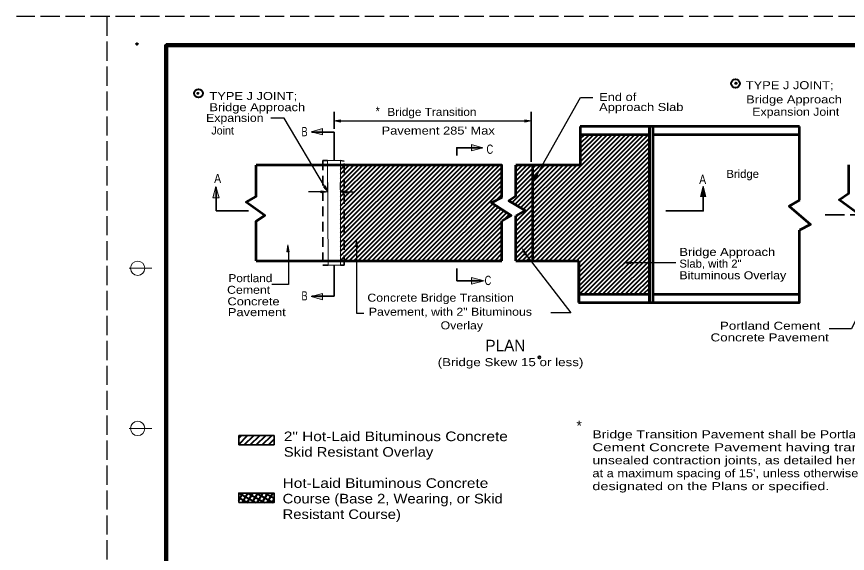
# Model space of a CAD drawing. Extents: x 36.4 to 71.7, y 0.5 to 22.5.
# Drawn here: x 36.4 to 50.93, y 13.09 to 22.48 of the extents above; entities that cross this region are included whole.
import ezdxf

# ---------------------------------------------------------------- set-up
doc = ezdxf.new("R2010")
doc.units = 0
doc.header["$LTSCALE"] = 0.056
doc.header["$PDMODE"] = 32
doc.header["$PDSIZE"] = 0.028
for name, pattern in [('LONG_DASH_SHORT_DASH', [9.9, 6, -1.2, 1.5, -1.2]), ('LONG_DASHED', [7.5, 6, -1.5]), ('MEDIUM_DASHED', [4.5, 3, -1.5])]:
    doc.linetypes.add(name, pattern=pattern)
for name, color, linetype, lineweight in [('1', 7, 'Continuous', 40), ('2', 7, 'MEDIUM_DASHED', 35), ('3', 7, 'Continuous', 13), ('5', 7, 'Continuous', 35), ('6', 7, 'Continuous', 13), ('7', 7, 'LONG_DASH_SHORT_DASH', 35)]:
    doc.layers.add(name, color=color, linetype=linetype, lineweight=lineweight)

msp = doc.modelspace()

# ---------------------------------------------------------------- hatches: boundary and pattern name
at = {"layer": '1'}
for points in [[(42.06308, 20.63383), (42.06308, 20.67133), (41.95058, 20.65258), (41.95058, 20.65258)], [(45.28767, 20.63383), (45.28767, 20.67133), (45.40017, 20.65258), (45.40017, 20.65258)], [(41.72817, 19.396), (41.72817, 19.4335), (41.84067, 19.41475), (41.84067, 19.41475)], [(42.1755, 19.396), (42.1755, 19.4335), (42.063, 19.41475), (42.063, 19.41475)]]:
    msp.add_hatch(color=256, dxfattribs=at).paths.add_polyline_path(points)
at = {"layer": '3'}
for points in [[(41.75125, 20.41192), (41.75125, 20.51883), (41.55192, 20.46525), (41.55192, 20.46525)], [(44.35408, 20.23875), (44.35408, 20.13192), (44.55333, 20.18542), (44.55333, 20.18542)], [(45.51292, 19.70658), (45.477, 19.72683), (45.43425, 19.60883), (45.43425, 19.60883)], [(39.83308, 19.30667), (39.94, 19.30667), (39.8865, 19.50592), (39.8865, 19.50592)], [(41.7995, 19.52108), (41.76733, 19.50192), (41.84075, 19.41475), (41.84075, 19.41475)], [(48.35692, 19.32992), (48.45408, 19.32992), (48.40542, 19.51108), (48.40542, 19.51108)], [(41.124, 18.362), (41.16525, 18.362), (41.14458, 18.48575), (41.14458, 18.48575)], [(42.32633, 18.4605), (42.36383, 18.4605), (42.345, 18.573), (42.345, 18.573)], [(45.28525, 18.30717), (45.318, 18.3255), (45.24675, 18.41458), (45.24675, 18.41458)], [(47.14017, 18.15467), (47.14017, 18.19592), (47.01642, 18.17533), (47.01642, 18.17533)], [(47.1415, 18.15467), (47.1415, 18.19592), (47.01775, 18.17533), (47.01775, 18.17533)], [(44.35625, 17.919), (44.35625, 17.80133), (44.57542, 17.86025), (44.57542, 17.86025)], [(41.74875, 17.52767), (41.74875, 17.6345), (41.54942, 17.581), (41.54942, 17.581)]]:
    msp.add_hatch(color=256, dxfattribs=at).paths.add_polyline_path(points)

# ---------------------------------------------------------------- linework, layer by layer
at = {"layer": '1', "linetype": 'LONG_DASHED', "lineweight": 25}
for p, q in [((71.60142, 22.47742), (36.40142, 22.47742)), ((37.97642, 22.47742), (37.97642, 0.47742))]:
    msp.add_line(p, q, dxfattribs=at)
at = {"layer": '1', "lineweight": 158}
for p, q in [((39.01808, 21.97742), (39.01808, 0.97742)), ((71.51808, 21.97742), (39.01808, 21.97742))]:
    msp.add_line(p, q, dxfattribs=at)
at = {"layer": '1', "lineweight": 35}
for p, q in [((41.95058, 20.5155), (41.95058, 20.81458)), ((45.40017, 19.93783), (45.40017, 20.81458)), ((40.28392, 15.1555), (40.28392, 14.98758)), ((40.90267, 15.1555), (40.28392, 15.1555)), ((40.90267, 14.98758), (40.90267, 15.1555)), ((40.28392, 14.98758), (40.90267, 14.98758))]:
    msp.add_line(p, q, dxfattribs=at)
at = {"layer": '1', "lineweight": 25}
for p, q in [((42.06308, 20.65258), (45.28767, 20.65258)), ((41.84075, 19.46308), (41.84075, 19.57675)), ((42.063, 19.447), (42.063, 19.57675)), ((41.61575, 19.41475), (41.50325, 19.41475)), ((41.72825, 19.41475), (41.61575, 19.41475)), ((42.1755, 19.41475), (42.288, 19.41475))]:
    msp.add_line(p, q, dxfattribs=at)
at = {"layer": '1', "lineweight": 53}
for p, q in [((46.25308, 20.55908), (46.25308, 19.88158)), ((50.08925, 20.55908), (46.25308, 20.55908)), ((50.09058, 20.55908), (46.25442, 20.55908)), ((47.46842, 17.47717), (47.46842, 20.55908)), ((47.46975, 17.47717), (47.46975, 20.55908)), ((47.53175, 17.47717), (47.53175, 20.55908)), ((47.53308, 17.47717), (47.53308, 20.55908)), ((50.09058, 19.27008), (50.09058, 20.55908)), ((47.46842, 20.413), (46.25308, 20.413)), ((47.46975, 20.413), (46.25442, 20.413)), ((50.08925, 20.413), (47.53175, 20.413)), ((50.09058, 20.413), (47.53308, 20.413)), ((45.12758, 19.33533), (45.12758, 19.88158)), ((45.42783, 18.20783), (45.42783, 19.88158)), ((44.88708, 18.20783), (44.88708, 18.90442)), ((45.12758, 18.20783), (45.12758, 18.99642)), ((40.58708, 18.20783), (44.88708, 18.20783)), ((45.12758, 18.20783), (46.22908, 18.20783)), ((46.22775, 18.20783), (46.22775, 17.47717)), ((46.22908, 18.20783), (46.22908, 17.47717)), ((46.22775, 17.62325), (47.46842, 17.62325)), ((46.22908, 17.62325), (47.46975, 17.62325)), ((47.53175, 17.62325), (50.08925, 17.62325)), ((47.53308, 17.62325), (50.09058, 17.62325))]:
    msp.add_line(p, q, dxfattribs=at)
at = {"layer": '1'}
for p, q in [((45.12758, 18.734), (46.80658, 20.413)), ((45.12758, 18.6545), (46.88617, 20.413)), ((45.12758, 18.57492), (46.96567, 20.413)), ((45.12758, 18.49533), (47.04517, 20.413)), ((45.12758, 18.41583), (47.12475, 20.413)), ((45.12758, 18.33633), (47.20425, 20.413)), ((45.12758, 18.25675), (47.28383, 20.413)), ((45.15817, 18.20783), (47.36333, 20.413)), ((45.23775, 18.20783), (47.44292, 20.413)), ((45.31725, 18.20783), (47.46975, 20.36033)), ((46.25442, 20.33808), (46.32925, 20.413)), ((46.25442, 20.25858), (46.40883, 20.413)), ((46.25442, 20.17908), (46.48833, 20.413)), ((46.25442, 20.0995), (46.56792, 20.413)), ((46.25442, 20.01992), (46.6475, 20.413)), ((46.25442, 19.94042), (46.727, 20.413)), ((45.39683, 18.20783), (47.46975, 20.28075)), ((45.47642, 18.20783), (47.46975, 20.20117)), ((45.55592, 18.20783), (47.46975, 20.12167)), ((45.6355, 18.20783), (47.46975, 20.04208)), ((45.71508, 18.20783), (47.46975, 19.9625)), ((42.06375, 18.21575), (43.72958, 19.88158)), ((42.06375, 18.29533), (43.65, 19.88158)), ((42.06375, 18.37483), (43.5705, 19.88158)), ((42.06375, 18.45442), (43.49092, 19.88158)), ((42.06375, 18.534), (43.41142, 19.88158)), ((42.06375, 18.6135), (43.33192, 19.88158)), ((42.06375, 18.69308), (43.25233, 19.88158)), ((42.06375, 18.77267), (43.17275, 19.88158)), ((42.06375, 18.85217), (43.09325, 19.88158)), ((42.06375, 18.93175), (43.01367, 19.88158)), ((42.06375, 19.01133), (42.93408, 19.88158)), ((42.06375, 19.09083), (42.85458, 19.88158)), ((42.06375, 19.17033), (42.775, 19.88158)), ((42.06375, 19.24992), (42.69542, 19.88158)), ((42.06375, 19.32942), (42.61592, 19.88158)), ((42.06375, 19.409), (42.53633, 19.88158)), ((42.06375, 19.48858), (42.45675, 19.88158)), ((42.06375, 19.56808), (42.37725, 19.88158)), ((42.06375, 19.64767), (42.29767, 19.88158)), ((42.06375, 19.72725), (42.21817, 19.88158)), ((42.06375, 19.80675), (42.13867, 19.88158)), ((42.13533, 18.20783), (43.80908, 19.88158)), ((42.21492, 18.20783), (43.88867, 19.88158)), ((42.29442, 18.20783), (43.96825, 19.88158)), ((42.374, 18.20783), (44.04775, 19.88158)), ((42.45358, 18.20783), (44.12733, 19.88158)), ((42.53308, 18.20783), (44.20692, 19.88158)), ((42.61267, 18.20783), (44.28642, 19.88158)), ((42.69217, 18.20783), (44.366, 19.88158)), ((42.77167, 18.20783), (44.44558, 19.88158)), ((42.85125, 18.20783), (44.52508, 19.88158)), ((42.93083, 18.20783), (44.60467, 19.88158)), ((43.01033, 18.20783), (44.68417, 19.88158)), ((43.08992, 18.20783), (44.76367, 19.88158)), ((43.1695, 18.20783), (44.84325, 19.88158)), ((43.249, 18.20783), (44.88708, 19.84583)), ((43.32858, 18.20783), (44.88708, 19.76633)), ((45.06025, 19.22358), (45.71833, 19.88158)), ((45.11008, 19.19383), (45.79792, 19.88158)), ((45.12758, 19.3705), (45.63883, 19.88158)), ((45.12758, 19.45), (45.55925, 19.88158)), ((45.12758, 19.52958), (45.47967, 19.88158)), ((45.12758, 19.60908), (45.40017, 19.88158)), ((45.12758, 19.68858), (45.32058, 19.88158)), ((45.12758, 19.76817), (45.241, 19.88158)), ((45.12758, 19.84775), (45.1615, 19.88158)), ((45.12758, 18.89317), (46.11608, 19.88158)), ((45.12758, 18.89317), (46.11608, 19.88158)), ((45.12758, 18.81358), (46.19558, 19.88158)), ((45.15992, 19.16417), (45.87742, 19.88158)), ((45.20983, 19.13442), (45.95692, 19.88158)), ((45.25967, 19.10475), (46.0365, 19.88158)), ((45.79458, 18.20783), (47.46975, 19.883)), ((45.87417, 18.20783), (47.46975, 19.80342)), ((43.40817, 18.20783), (44.88708, 19.68675)), ((45.95375, 18.20783), (47.46975, 19.72383)), ((46.03325, 18.20783), (47.46975, 19.64433)), ((43.48767, 18.20783), (44.88708, 19.60717)), ((43.56725, 18.20783), (44.88708, 19.52767)), ((46.11283, 18.20783), (47.46975, 19.56483)), ((46.19242, 18.20783), (47.46975, 19.48525)), ((43.64683, 18.20783), (44.88708, 19.44808)), ((44.77675, 19.25817), (44.88708, 19.3685)), ((46.22908, 18.165), (47.46975, 19.40575)), ((46.22908, 18.08542), (47.46975, 19.32617)), ((43.72633, 18.20783), (44.72467, 19.20625)), ((43.80592, 18.20783), (44.77292, 19.17483)), ((45.01042, 19.25317), (45.02917, 19.27192)), ((46.22908, 18.00583), (47.46975, 19.24667)), ((43.88542, 18.20783), (44.82117, 19.14358)), ((43.96492, 18.20783), (44.86942, 19.11225)), ((44.0445, 18.20783), (44.91758, 19.08092)), ((44.124, 18.20783), (44.96583, 19.04958)), ((46.22908, 17.92633), (47.46975, 19.16708)), ((46.22908, 17.84675), (47.46975, 19.0875)), ((44.20358, 18.20783), (44.88708, 18.89125)), ((44.9195, 18.92358), (45.01408, 19.01825)), ((45.12758, 18.97267), (45.18075, 19.02592)), ((46.22908, 17.76717), (47.46975, 19.008)), ((46.22908, 17.68767), (47.46975, 18.92842)), ((44.28317, 18.20783), (44.88708, 18.81175)), ((46.24425, 17.62325), (47.46975, 18.84883)), ((46.32375, 17.62325), (47.46975, 18.76933)), ((44.36267, 18.20783), (44.88708, 18.73217)), ((44.44225, 18.20783), (44.88708, 18.65258)), ((46.40333, 17.62325), (47.46975, 18.68975)), ((46.48283, 17.62325), (47.46975, 18.61017)), ((44.52183, 18.20783), (44.88708, 18.57308)), ((44.60133, 18.20783), (44.88708, 18.4935)), ((46.56242, 17.62325), (47.46975, 18.53067)), ((46.642, 17.62325), (47.46975, 18.45108)), ((44.68092, 18.20783), (44.88708, 18.41392)), ((44.7605, 18.20783), (44.88708, 18.33442)), ((46.7215, 17.62325), (47.46975, 18.37158)), ((44.84, 18.20783), (44.88708, 18.25483)), ((46.80108, 17.62325), (47.46975, 18.29208)), ((46.88067, 17.62325), (47.46975, 18.2125)), ((46.96017, 17.62325), (47.46975, 18.13292)), ((47.03975, 17.62325), (47.46975, 18.05342)), ((47.11933, 17.62325), (47.46975, 17.97383)), ((47.19883, 17.62325), (47.46975, 17.89425)), ((47.27842, 17.62325), (47.46975, 17.81475)), ((47.35792, 17.62325), (47.46975, 17.73517)), ((47.43742, 17.62325), (47.46975, 17.65558)), ((40.28392, 14.99842), (40.441, 15.1555)), ((40.28392, 15.1045), (40.335, 15.1555)), ((40.37917, 14.98758), (40.54708, 15.1555)), ((40.48533, 14.98758), (40.65317, 15.1555)), ((40.59142, 14.98758), (40.75917, 15.1555)), ((40.69742, 14.98758), (40.86533, 15.1555)), ((40.8035, 14.98758), (40.90267, 15.08692)), ((40.28392, 14.01892), (40.35858, 14.14825)), ((40.29458, 14.14825), (40.58542, 13.98033)), ((40.34833, 13.98033), (40.44517, 14.14825)), ((40.43492, 13.98033), (40.53183, 14.14825)), ((40.44458, 14.14825), (40.73542, 13.98033)), ((40.5215, 13.98033), (40.61842, 14.14825)), ((40.59458, 14.14825), (40.88542, 13.98033)), ((40.60808, 13.98033), (40.705, 14.14825)), ((40.69467, 13.98033), (40.79158, 14.14825)), ((40.74458, 14.14825), (40.90267, 14.05692)), ((40.78133, 13.98033), (40.87817, 14.14825)), ((40.89458, 14.14825), (40.90267, 14.1435)), ((40.28392, 14.06775), (40.43542, 13.98033)), ((40.28392, 13.98108), (40.28542, 13.98033)), ((40.86792, 13.98033), (40.90267, 14.04075))]:
    msp.add_line(p, q, dxfattribs=at)
at = {"layer": '1', "lineweight": 13}
for p, q in [((42.06375, 19.88158), (42.06375, 18.20783)), ((38.76808, 18.07742), (38.36808, 18.07742)), ((38.76808, 15.27742), (38.36808, 15.27742))]:
    msp.add_line(p, q, dxfattribs=at)
for points in [[(42.06308, 20.63383), (42.06308, 20.67133), (41.95058, 20.65258), (41.95058, 20.65258)], [(45.28767, 20.63383), (45.28767, 20.67133), (45.40017, 20.65258), (45.40017, 20.65258)], [(41.84708, 18.13417), (42.06308, 18.13417), (42.06308, 19.96125), (41.83808, 19.96125)]]:
    msp.add_lwpolyline(points, close=True, dxfattribs=at)
at = {"layer": '1', "lineweight": 53}
for points in [[(46.25442, 20.55908), (46.25442, 19.88158), (45.12758, 19.88158)], [(40.58708, 18.20783), (40.58708, 18.89925), (40.74008, 18.99825), (40.41608, 19.23225), (40.58708, 19.33125), (40.58708, 19.88158)], [(44.88708, 19.316), (44.88708, 19.88158), (40.58708, 19.88158)], [(51.14917, 19.00392), (50.7805, 19.27175), (50.95067, 19.38883), (50.95067, 19.88608)], [(45.12758, 19.33533), (45.005, 19.25642), (45.29025, 19.0865), (45.12758, 18.99642)], [(44.88708, 19.316), (44.70367, 19.21983), (45.04517, 18.99808), (44.88708, 18.90442)], [(50.09058, 19.27008), (49.90608, 19.16392), (50.28133, 18.84567), (50.09058, 18.74283)], [(46.22775, 17.47717), (50.08925, 17.47717), (50.08925, 18.74283)], [(46.22908, 17.47717), (50.09058, 17.47717), (50.09058, 18.74283)]]:
    msp.add_lwpolyline(points, dxfattribs=at)
at = {"layer": '1', "lineweight": 25}
for points in [[(41.72817, 19.396), (41.72817, 19.4335), (41.84067, 19.41475), (41.84067, 19.41475)], [(42.1755, 19.396), (42.1755, 19.4335), (42.063, 19.41475), (42.063, 19.41475)]]:
    msp.add_lwpolyline(points, close=True, dxfattribs=at)
at = {"layer": '1', "lineweight": 35}
msp.add_lwpolyline([(40.28392, 13.98033), (40.90267, 13.98033), (40.90267, 14.14825), (40.28392, 14.14825)], close=True, dxfattribs=at)
at = {"layer": '1', "lineweight": 13}
for centre in [(38.51808, 18.07742), (38.51808, 15.27742)]:
    msp.add_circle(centre, 0.125, dxfattribs=at)
at = {"layer": '1'}
for p in [(38.50608, 21.99742), (39.01808, 21.97742)]:
    msp.add_point(p, dxfattribs=at)
at = {"layer": '2'}
for points in [[(41.83808, 19.96125), (41.757, 19.96125), (41.757, 18.13417), (41.84708, 18.13417)], [(42.06308, 18.13417), (42.12608, 18.13417), (42.12608, 19.95217), (42.06308, 19.96125)]]:
    msp.add_lwpolyline(points, dxfattribs=at)
at = {"layer": '3', "lineweight": 25}
for p, q in [((47.14358, 18.17567), (47.92508, 18.17567)), ((47.14492, 18.17567), (47.92642, 18.17567))]:
    msp.add_line(p, q, dxfattribs=at)
for points in [[(45.483, 19.68908), (46.25808, 21.06508), (46.47358, 21.06508)], [(41.78342, 19.51158), (41.0775, 20.7025), (40.84875, 20.7025)], [(42.34508, 18.46058), (42.34508, 17.29225), (42.46967, 17.29225)], [(41.15383, 18.36642), (41.15383, 17.79108), (40.864, 17.79108)], [(45.30158, 18.31633), (46.08867, 17.29883), (45.74342, 17.29883)], [(51.68808, 18.40858), (50.99792, 17.0205), (50.60792, 17.0205)]]:
    msp.add_lwpolyline(points, dxfattribs=at)
at = {"layer": '3'}
for points in [[(41.75125, 20.41192), (41.75125, 20.51883), (41.55192, 20.46525), (41.55192, 20.46525)], [(44.35408, 20.23875), (44.35408, 20.13192), (44.55333, 20.18542), (44.55333, 20.18542)], [(45.51292, 19.70658), (45.477, 19.72683), (45.43425, 19.60883), (45.43425, 19.60883)], [(39.83308, 19.30667), (39.94, 19.30667), (39.8865, 19.50592), (39.8865, 19.50592)], [(41.7995, 19.52108), (41.76733, 19.50192), (41.84075, 19.41475), (41.84075, 19.41475)], [(48.35692, 19.32992), (48.45408, 19.32992), (48.40542, 19.51108), (48.40542, 19.51108)], [(41.124, 18.362), (41.16525, 18.362), (41.14458, 18.48575), (41.14458, 18.48575)], [(42.32633, 18.4605), (42.36383, 18.4605), (42.345, 18.573), (42.345, 18.573)], [(45.28525, 18.30717), (45.318, 18.3255), (45.24675, 18.41458), (45.24675, 18.41458)], [(47.14017, 18.15467), (47.14017, 18.19592), (47.01642, 18.17533), (47.01642, 18.17533)], [(47.1415, 18.15467), (47.1415, 18.19592), (47.01775, 18.17533), (47.01775, 18.17533)], [(44.35625, 17.919), (44.35625, 17.80133), (44.57542, 17.86025), (44.57542, 17.86025)], [(41.74875, 17.52767), (41.74875, 17.6345), (41.54942, 17.581), (41.54942, 17.581)]]:
    msp.add_lwpolyline(points, close=True, dxfattribs=at)
at = {"layer": '3', "lineweight": 40}
for centre, radius in [((48.96973, 21.30742), 0.0741), ((39.58004, 21.13612), 0.07517), ((48.97607, 21.31367), 0.01235), ((39.57154, 21.13604), 0.0094)]:
    msp.add_circle(centre, radius, dxfattribs=at)
at = {"layer": '3', "lineweight": 35}
msp.add_circle((45.54242, 16.51967), 0.02052, dxfattribs=at)
at = {"layer": '5'}
for p, q in [((41.5655, 20.45925), (41.95058, 20.45925)), ((41.95058, 19.96125), (41.95058, 20.45925)), ((39.89142, 19.49217), (39.89142, 19.08025)), ((40.45842, 19.08025), (39.89142, 19.08025)), ((41.95508, 18.13417), (41.95508, 17.58825)), ((44.09533, 17.85825), (44.09533, 18.07533)), ((44.54058, 17.85825), (44.09533, 17.85825)), ((41.5655, 17.58825), (41.95508, 17.58825))]:
    msp.add_line(p, q, dxfattribs=at)
for points in [[(44.54058, 20.18533), (44.09533, 20.18533), (44.09533, 20.05067)], [(48.40542, 19.49217), (48.40542, 19.08025), (47.75083, 19.08025)]]:
    msp.add_lwpolyline(points, dxfattribs=at)
at = {"layer": '6'}
for p, q in [((45.40017, 20.65258), (45.40025, 20.65258)), ((41.95058, 20.45925), (41.95067, 20.45925)), ((45.40017, 19.88158), (45.40025, 19.88158))]:
    msp.add_line(p, q, dxfattribs=at)
at = {"layer": '6', "lineweight": 25}
for p, q in [((41.84075, 19.41475), (41.84083, 19.41475)), ((41.84075, 19.40683), (41.84083, 19.40683)), ((42.063, 19.39075), (42.06308, 19.39075))]:
    msp.add_line(p, q, dxfattribs=at)
at = {"layer": '7'}
msp.add_line((50.53942, 19.01133), (60.50117, 19.01133), dxfattribs=at)

# ---------------------------------------------------------------- texts
at = {"layer": '1', "width": 1.1}
msp.add_text('Bridge Transition', height=0.14, dxfattribs=at).set_placement((42.884, 20.74092))
at = {"layer": '3'}
for s, height, width, p in [('TYPE J JOINT;', 0.14, 1.2, (49.15042, 21.20858)), ('TYPE J JOINT;', 0.14, 1.2, (39.77233, 21.01975)), ('End of', 0.14, 1.2, (46.58608, 21.00208)), ('Bridge Approach', 0.14, 1.2, (49.15667, 20.96033)), ('Bridge Approach', 0.14, 1.2, (39.77233, 20.82375)), ('Approach Slab', 0.14, 1.2, (46.58608, 20.82625)), ('Expansion', 0.14, 1.15, (39.71367, 20.63675)), ('*', 0.162, 0.85, (42.67883, 20.7425)), ('Expansion Joint', 0.14, 1.15, (49.26392, 20.74383)), ("Pavement 285' Max", 0.14, 1.2, (42.78317, 20.41492)), ('Bridge', 0.14, 1.05, (48.81117, 19.658)), ('Bridge', 0.14, 1.05, (48.8125, 19.658)), ('Bridge Approach', 0.14, 1.2, (47.98892, 18.29292)), ('Bridge Approach', 0.14, 1.2, (47.99025, 18.29292)), ('Slab, with 2"', 0.14, 1.05, (47.98892, 18.08892)), ('Slab, with 2"', 0.14, 1.05, (47.99025, 18.08892)), ('Bituminous Overlay', 0.14, 1.15, (47.98892, 17.88492)), ('Bituminous Overlay', 0.14, 1.15, (47.99025, 17.88492)), ('Portland', 0.14, 1.1, (40.10517, 17.83458)), ('Cement', 0.14, 1.15, (40.08067, 17.63075)), ('Concrete Bridge Transition', 0.14, 1.15, (42.53375, 17.49342)), ('Concrete', 0.14, 1.2, (40.0875, 17.429)), ('Pavement', 0.14, 1.2, (40.095, 17.2405)), ('Pavement, with 2" Bituminous', 0.14, 1.15, (42.55908, 17.24733)), ('Overlay', 0.14, 1.15, (43.81392, 17.00958)), ('Portland Cement', 0.14, 1.25, (48.69783, 17.00267)), ('Concrete Pavement', 0.14, 1.25, (48.534, 16.79867)), ('(Bridge Skew 15 or less)', 0.14, 1.25, (43.76242, 16.36592)), ('Bridge Transition Pavement shall be Portland', 0.14, 1.3, (46.46817, 15.10467)), ('2" Hot-Laid Bituminous Concrete', 0.168, 1.2, (41.07333, 15.05483)), ('Cement Concrete Pavement having transverse,', 0.14, 1.4, (46.46817, 14.878)), ('Skid Resistant Overlay', 0.168, 1.15, (41.07333, 14.78283)), ('unsealed contraction joints, as detailed herein,', 0.14, 1.3, (46.46817, 14.65133)), ("at a maximum spacing of 15', unless otherwise", 0.14, 1.2, (46.46817, 14.42467)), ('Hot-Laid Bituminous Concrete', 0.168, 1.2, (41.05208, 14.23775)), ('designated on the Plans or specified.', 0.14, 1.35, (46.46817, 14.198)), ('Course (Base 2, Wearing, or Skid', 0.168, 1.15, (41.05208, 13.96575)), ('Resistant Course)', 0.168, 1.15, (41.05208, 13.69375))]:
    msp.add_text(s, height=height, dxfattribs=dict(at, width=width)).set_placement(p)
for s, height, p in [('Joint', 0.14, (39.80567, 20.41583)), ('PLAN', 0.2, (44.59742, 16.62683)), ('*', 0.18, (46.18942, 15.23467))]:
    msp.add_text(s, height=height, dxfattribs=at).set_placement(p)
at = {"layer": '5'}
for s, width, p in [('B', 0.75, (41.38125, 20.38508)), ('C', 0.75, (44.61642, 20.07842)), ('A', 0.85, (39.8545, 19.56625)), ('A', 0.85, (48.3345, 19.54917)), ('C', 0.75, (44.58317, 17.78408)), ('B', 0.75, (41.38125, 17.51408))]:
    msp.add_text(s, height=0.162, dxfattribs=dict(at, width=width)).set_placement(p)

doc.saveas('drawing.dxf')
